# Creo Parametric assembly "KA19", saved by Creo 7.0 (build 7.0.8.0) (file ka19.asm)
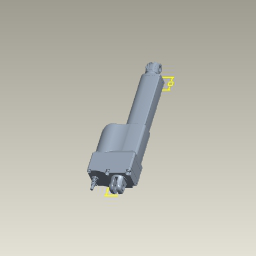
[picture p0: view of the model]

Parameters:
  PTC_COMMON_NAME = "1079w4001.asm"
  PTC_WM_ITERATION = "1"
  PTC_WM_VERSION = "A.1"
  PTC_WM_LIFECYCLE_STATE = "Concept"
  PTC_WM_LIFECYCLE = "Life Cycle Schema Type 1"
  PTC_WM_LOCATION = "/Products/KA19_CN2215/CAD"
  PTC_WM_CREATED_BY = "Jörg Monien"
  PTC_WM_CREATED_ON = "2026-08-11"
  PTC_WM_MODIFIED_BY = "Jörg Monien"
  PTC_WM_MODIFIED_ON = "2026-08-11"
  PTC_WM_NUMBER = "KA19.ASM"
  PDMRL = "Concept"
  PROI_REVISION = "A"
  PROI_VERSION = "1"
  PROI_RELEASE = "Concept"

Other parameters: BID, STROKE, ORIENTATION, D1, D5, D9, D14

Created from: 1079W4001.ASM

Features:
  1. datum plane "ASM_RIGHT"
  2. datum plane "ASM_TOP"
  3. datum plane "ASM_FRONT"
  4. coordinate system
  5. datum axis
  6. datum axis
  7. datum axis
  8. datum plane "BACKFIXTURE-DATA"
  9. datum plane "BID-DATA"
  10. datum plane "OUTER-TUBE-DATA"
  11. datum plane "STROKE"
  12. datum plane "ORIENTATION-DATA"
  13. datum plane "ORIENTATION-NORMAL"
  14. coordinate system
  15. coordinate system
  16. coordinate system
  17. component "KA-19-H"
  18. component "KA-19-PR"
  19. component "KA-19-OT"
  20. component "KA19-BF"
  21. component "KA-19-BF-METALL"
  22. component "KA-19-PR-SLOT"
  23. component "1079W4001-PR-MS.PRT"

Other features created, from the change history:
  component "1079W4001-OT.PRT"
  component "KA-19-BF-METALL.PRT"
  component "KA-19-PR-SLOT.PRT"

Other named items: PISTON-ROD-PLACEMENT, BACK-FIXTURE-PLACEMENT, OUTER-TUBE-PLACEMENT, DATUMS, X-AXES, Y-AXES, Z-AXES, ACS0, DRV_DIM_D8, D8, DRV_DIM_D13, D13, NOTE_0, BF-PRMS

Notes: PARAMETERS: | BID =  | 300.0 | STROKE =  | ORIENTATION =  | NOTE: | Standard aktuator | BID = 150+Stroke+2 | Stroke =BID-150-2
